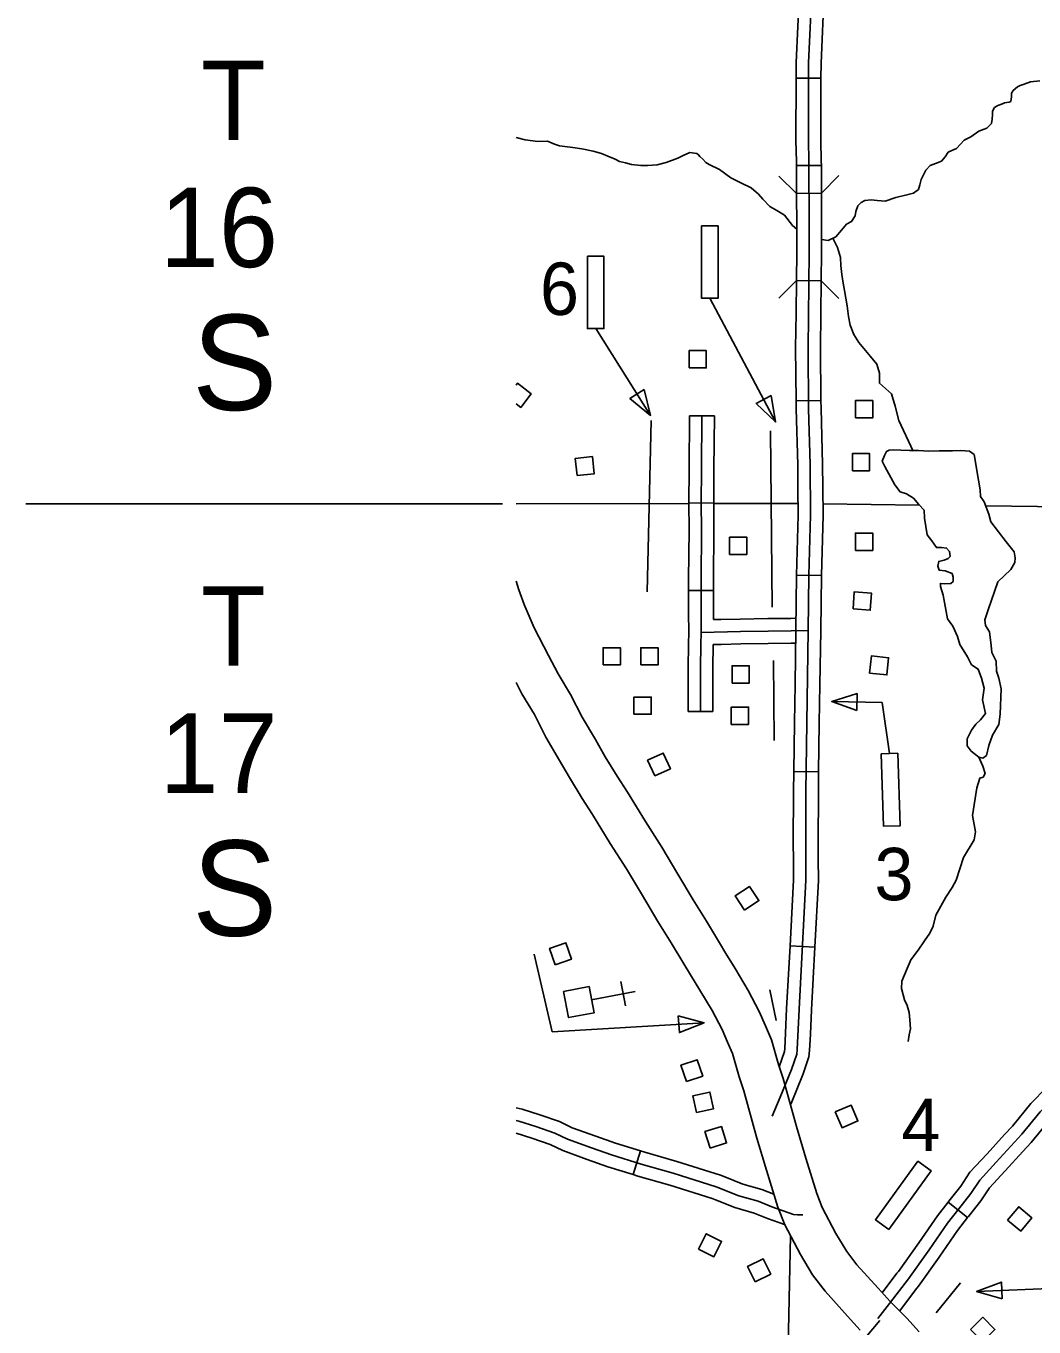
# Model space of a CAD drawing. Extents: x 61396 to 64680, y 55472 to 57605.
# Drawn here: x 61823 to 62013.4, y 56228.4 to 56474.2 of the extents above; entities that cross this region are included whole.
import ezdxf

# ---------------------------------------------------------------- set-up
doc = ezdxf.new("R2010")
doc.units = 0
for name, color, linetype in [('10', 7, 'Continuous'), ('31', 7, 'Continuous'), ('32', 7, 'Continuous'), ('35', 7, 'Continuous'), ('38', 7, 'Continuous'), ('4', 7, 'Continuous'), ('56', 7, 'Continuous'), ('57', 7, 'Continuous'), ('R_Border Notes', 7, 'Continuous')]:
    doc.layers.add(name, color=color, linetype=linetype)

msp = doc.modelspace()

# ---------------------------------------------------------------- linework, layer by layer
at = {"layer": '10'}
for points in [[(61915.57, 56369.32), (61916.11, 56367.7), (61917.13, 56364.9), (61919.02, 56360.49), (61921.72, 56355.3), (61923.52, 56351.83), (61925.86, 56347.92), (61928.07, 56343.61), (61930.55, 56339.39), (61932.4, 56336.16), (61934.64, 56332.45), (61936.63, 56329.45), (61940, 56323.91), (61943.08, 56319.06), (61946.13, 56313.95), (61949.05, 56309.13), (61951.52, 56305.1), (61953.99, 56301.03), (61955.18, 56299), (61956.98, 56296.16), (61959.42, 56292.03), (61960.13, 56290.68), (61961.52, 56288.06), (61962.72, 56285.33), (61963.81, 56282.68), (61965.17, 56278.03), (61966.06, 56275.35), (61968.55, 56266.29), (61970.34, 56260.35), (61972.38, 56253.66), (61973.43, 56251.02), (61976, 56246.11)], [(61969.28, 56242.13), (61966.32, 56247.75), (61965, 56251.07), (61962.86, 56258.08), (61961.04, 56264.13), (61958.59, 56273.07), (61957.71, 56275.7), (61956.43, 56280.09), (61955.53, 56282.27), (61954.48, 56284.65), (61953.23, 56287.02), (61952.6, 56288.2), (61950.31, 56292.08), (61948.51, 56294.94), (61947.28, 56297.04), (61944.85, 56301.03), (61942.38, 56305.06), (61939.44, 56309.92), (61936.42, 56314.96), (61933.37, 56319.78), (61930.03, 56325.26), (61928.04, 56328.27), (61925.66, 56332.2), (61923.79, 56335.47), (61921.22, 56339.85), (61919.03, 56344.13), (61916.69, 56348.02), (61915.57, 56350.18)], [(61976, 56246.11), (61978.03, 56242.7), (61979.97, 56240.21), (61983.98, 56235.75), (61986.26, 56233.24), (61989.38, 56230.08), (61991.73, 56227.55)], [(61980.58, 56227.86), (61978.18, 56230.51), (61973.97, 56235.19), (61971.56, 56238.29), (61969.28, 56242.13)]]:
    msp.add_lwpolyline(points, dxfattribs=at)
at = {"layer": '31'}
for p, q in [((61968.58, 56442.52), (61973.26, 56442.59)), ((61973.23, 56426.04), (61968.54, 56426.07)), ((61973.18, 56403.43), (61968.49, 56403.38)), ((61968.57, 56370.44), (61973.25, 56370.39)), ((61968.57, 56370.44), (61973.25, 56370.39)), ((61968.05, 56333.35), (61972.73, 56333.29)), ((61972.01, 56300.21), (61967.33, 56300.46)), ((61939.07, 56261.71), (61937.69, 56257.23)), ((62000.89, 56249.1), (61997.2, 56252))]:
    msp.add_line(p, q, dxfattribs=at)
for points in [[(61968.58, 56442.52), (61968.6, 56436.4)], [(61973.26, 56442.59), (61973.29, 56436.41)], [(61968.6, 56436.4), (61968.61, 56431.47), (61968.54, 56426.07)], [(61970.94, 56436.4), (61970.96, 56431.45), (61970.73, 56413.35), (61970.85, 56401.88), (61971.13, 56391.35), (61971.22, 56381.78), (61970.91, 56370.43), (61970.78, 56360)], [(61973.29, 56436.41), (61973.3, 56431.44), (61973.23, 56426.04)], [(61968.54, 56426.07), (61968.47, 56419.94)], [(61973.23, 56426.04), (61973.15, 56419.88)], [(61968.47, 56419.94), (61968.38, 56413.36), (61968.49, 56403.38)], [(61973.15, 56419.88), (61973.07, 56413.35), (61973.18, 56403.43)], [(61968.49, 56403.38), (61968.51, 56401.83), (61968.78, 56391.31), (61968.82, 56386.89)], [(61973.51, 56386.93), (61973.47, 56391.4), (61973.19, 56401.92), (61973.18, 56403.43)], [(61968.82, 56386.89), (61968.87, 56381.8), (61968.57, 56370.47), (61968.57, 56370.44)], [(61973.25, 56370.39), (61973.25, 56370.39), (61973.56, 56381.76), (61973.51, 56386.93)], [(61968.57, 56370.44), (61968.44, 56360.03)], [(61973.25, 56370.39), (61973.13, 56359.97)], [(61963.96, 56268.26), (61965.49, 56271.87), (61967.61, 56277.07), (61968.6, 56279.95), (61968.7, 56280.85), (61969.03, 56288.48), (61970.34, 56312.81), (61970.29, 56319.78), (61970.34, 56329.52), (61970.5, 56342.54), (61970.78, 56360)], [(61968.28, 56349.85), (61968.44, 56360.04)], [(61972.96, 56349.78), (61973.13, 56359.96)], [(61968.05, 56333.35), (61968.16, 56342.57), (61968.28, 56349.85)], [(61972.73, 56333.29), (61972.85, 56342.51), (61972.96, 56349.78)], [(61967.97, 56316.8), (61967.94, 56319.77), (61968, 56329.55), (61968.05, 56333.35)], [(61972.73, 56333.29), (61972.68, 56329.5), (61972.63, 56319.78), (61972.65, 56316.84)], [(61967.33, 56300.46), (61968, 56312.86), (61967.97, 56316.8)], [(61972.65, 56316.84), (61972.69, 56312.75), (61972.01, 56300.21)], [(61966.49, 56283.96), (61966.69, 56288.59), (61967.33, 56300.46)], [(61971.17, 56283.75), (61971.37, 56288.37), (61972.01, 56300.21)], [(62046.84, 56295.38), (62045.24, 56293.73), (62043.16, 56291.98), (62041.18, 56290.72), (62037.4, 56288.42), (62033.29, 56285.65), (62028.75, 56282.3), (62026.21, 56280.34), (62023.78, 56278.1), (62020.38, 56274.99), (62014.6, 56269.06), (62011.11, 56264.86), (62006.28, 56259.55), (62003.17, 56256.2), (62001.5, 56253.67), (61999.2, 56250.75), (61997.1, 56248.08), (61993.61, 56243.01), (61989.69, 56237.56), (61986.15, 56232.88), (61983.9, 56230.07)], [(61965.3, 56277.58), (61966.3, 56280.45), (61966.36, 56281.02), (61966.49, 56283.96)], [(61967.42, 56270.41), (61967.65, 56270.97), (61969.8, 56276.24), (61970.91, 56279.44), (61971.03, 56280.69), (61971.17, 56283.75)], [(62007.86, 56264.77), (62009.34, 56266.39), (62012.85, 56270.63), (62018.75, 56276.67), (62019.17, 56277.06)], [(62022.34, 56273.6), (62022.01, 56273.31), (62016.34, 56267.49), (62012.88, 56263.32), (62011.33, 56261.62)], [(61915.57, 56269.86), (61916.71, 56269.6), (61920.04, 56268.54), (61923.76, 56267.25), (61923.88, 56267.19)], [(61969.77, 56249.64), (61968.73, 56249.61), (61967.97, 56249.68), (61963.91, 56251.16), (61961.28, 56252.18), (61957.66, 56253.21), (61953.39, 56254.94), (61945.26, 56257.48), (61939.22, 56259.21), (61933.63, 56260.93), (61929.81, 56262.29), (61925.3, 56263.93), (61922.87, 56265.08), (61919.3, 56266.31), (61916.1, 56267.34), (61915.57, 56267.46)], [(61921.99, 56262.91), (61918.56, 56264.09), (61915.57, 56265.05)], [(61923.88, 56267.19), (61926.2, 56266.09), (61930.61, 56264.49), (61934.37, 56263.16), (61939.07, 56261.71)], [(61937.69, 56257.23), (61932.9, 56258.71), (61929.02, 56260.08), (61924.39, 56261.76), (61921.99, 56262.91)], [(61997.2, 56252), (61997.36, 56252.2), (61999.6, 56255.04), (62001.32, 56257.66), (62004.55, 56261.14), (62007.86, 56264.77)], [(61955.03, 56256.8), (61954.18, 56257.14), (61945.93, 56259.73), (61939.89, 56261.45), (61939.07, 56261.71)], [(62011.33, 56261.62), (62008, 56257.96), (62005.02, 56254.75), (62003.4, 56252.3), (62001.05, 56249.31), (62000.89, 56249.1)], [(61953.27, 56252.46), (61952.6, 56252.73), (61944.59, 56255.24), (61938.55, 56256.96), (61937.69, 56257.23)], [(61964.25, 56253.54), (61962.03, 56254.41), (61958.43, 56255.43), (61955.03, 56256.8)], [(61966.31, 56247.79), (61963.08, 56248.96), (61960.53, 56249.96), (61956.9, 56250.99), (61953.27, 56252.46)], [(61997.2, 56252), (61995.21, 56249.47), (61991.69, 56244.36), (61987.8, 56238.95), (61987.53, 56238.58)], [(62000.89, 56249.1), (61998.99, 56246.69), (61995.53, 56241.66), (61991.58, 56236.17), (61991.27, 56235.76)], [(61987.53, 56238.58), (61984.75, 56234.9)], [(61991.27, 56235.76), (61988.02, 56231.46)], [(61930.45, 56183.74), (61933.97, 56184.15), (61937.57, 56184.89), (61940, 56186.02), (61943.65, 56188.21), (61947.9, 56191.9), (61951.41, 56194.9), (61959.17, 56201.91), (61965.24, 56207.61), (61969.78, 56212.7), (61976.27, 56219.95), (61980.01, 56224.58), (61984.28, 56229.68)]]:
    msp.add_lwpolyline(points, dxfattribs=at)
at = {"layer": '32'}
for p, q in [((61968.49, 56464.33), (61973.18, 56464.31)), ((61968.56, 56447.81), (61973.25, 56447.83)), ((61948.35, 56400.57), (61953.04, 56400.53)), ((61948.22, 56384.03), (61952.91, 56384.08)), ((61948.17, 56367.55), (61952.86, 56367.55)), ((61952.77, 56344.72), (61948.08, 56344.72))]:
    msp.add_line(p, q, dxfattribs=at)
for points in [[(62009.57, 56550.11), (62005.52, 56536.02), (62001.49, 56522.36), (62000.08, 56516.98), (61999.59, 56515.45), (61998.01, 56513.39), (61992.08, 56507.78), (61983.37, 56500.49), (61976.84, 56495.43), (61974.77, 56493.31), (61973.36, 56490.86), (61972.6, 56488.52), (61971.52, 56481.91), (61970.84, 56467.24), (61970.79, 56452.56), (61970.9, 56448.61), (61970.94, 56436.4)], [(61969.13, 56480.91), (61968.5, 56467.3), (61968.49, 56464.33)], [(61973.81, 56480.7), (61973.19, 56467.18), (61973.18, 56464.31)], [(61968.49, 56464.33), (61968.44, 56452.53), (61968.56, 56448.57), (61968.56, 56447.81)], [(61973.18, 56464.31), (61973.13, 56452.59), (61973.24, 56448.65), (61973.25, 56447.83)], [(61968.56, 56447.81), (61968.58, 56442.52)], [(61973.25, 56447.83), (61973.26, 56442.59)], [(61948.35, 56400.57), (61948.25, 56390.44), (61948.22, 56384.12), (61948.22, 56384.03)], [(61950.69, 56400.55), (61950.59, 56390.42), (61950.57, 56384.13), (61950.62, 56379), (61950.51, 56369.59), (61950.51, 56363.35), (61950.54, 56359.64)], [(61953.04, 56400.53), (61952.94, 56390.4), (61952.91, 56384.14), (61952.91, 56384.08)], [(61948.22, 56384.03), (61948.27, 56379), (61948.17, 56369.6), (61948.17, 56367.55)], [(61952.91, 56384.08), (61952.96, 56379), (61952.86, 56369.58), (61952.86, 56367.55)], [(61948.17, 56367.55), (61948.17, 56363.34), (61948.19, 56359.69)], [(61952.86, 56367.55), (61952.86, 56363.36), (61952.87, 56362.04)], [(61954.23, 56362.07), (61952.87, 56362.04)], [(61968.47, 56362.3), (61967.49, 56362.29), (61963.16, 56362.23), (61957.92, 56362.16), (61954.23, 56362.07)], [(61948.08, 56344.72), (61948.08, 56349.21), (61948.08, 56352.89), (61948.14, 56357.4), (61948.19, 56359.69)], [(61950.43, 56344.72), (61950.43, 56349.21), (61950.43, 56352.87), (61950.48, 56357.36), (61950.54, 56359.64)], [(61970.78, 56360), (61967.52, 56359.94), (61963.19, 56359.89), (61957.96, 56359.81), (61950.54, 56359.64)], [(61952.77, 56344.72), (61952.77, 56349.21), (61952.77, 56352.86), (61952.83, 56357.35)], [(61954.34, 56357.38), (61952.83, 56357.35)], [(61968.4, 56357.61), (61967.55, 56357.6), (61963.22, 56357.55), (61958.01, 56357.47), (61954.34, 56357.38)]]:
    msp.add_lwpolyline(points, dxfattribs=at)
at = {"layer": '35'}
for points in [[(62014.55, 56463.82), (62012.79, 56463.61), (62011.56, 56463.2), (62010.8, 56462.91), (62010.33, 56462.7), (62009.5, 56461.97), (62009.14, 56461.5), (62009.15, 56460.78), (62009.04, 56459.94), (62008.75, 56459.76), (62007.88, 56459.68), (62007.49, 56459.44), (62006.61, 56459.15), (62005.97, 56458.76), (62005.61, 56458.11), (62005.57, 56457.45), (62005.52, 56456.6), (62005.37, 56455.73), (62004.5, 56454.87), (62003.02, 56454.28), (62001.46, 56453.22), (62000.25, 56452.59), (61998.78, 56451.03), (61997.89, 56450.67), (61997.22, 56450.31), (61996.64, 56449.48), (61995.93, 56448.62), (61994.82, 56448.17), (61993.78, 56447.82), (61992.98, 56446.93), (61992.12, 56445.17), (61991.88, 56444.14), (61991.58, 56443.3), (61990.65, 56442.57), (61989.42, 56442.28), (61987.34, 56441.8), (61985.29, 56441.1), (61983.79, 56441.23)], [(61968.61, 56435.77), (61967.81, 56436.48), (61966.26, 56438.43), (61964.81, 56439.35), (61963.52, 56440.1), (61962.17, 56441.45), (61961.35, 56442.39), (61959.97, 56443.58), (61958.02, 56444.57), (61956.17, 56445.5), (61954.01, 56447.09), (61952.06, 56447.98), (61951.42, 56448.41), (61950.84, 56448.99), (61950.29, 56449.5), (61950.04, 56449.85), (61949.7, 56450.08), (61948.43, 56450.27), (61947.16, 56449.71), (61946.15, 56449.2), (61943.94, 56448.41), (61942.2, 56447.95), (61940.48, 56447.8), (61939.13, 56447.84), (61937.38, 56448.04), (61936.23, 56448.35), (61935.08, 56448.56), (61934.28, 56449.02), (61932.88, 56449.59), (61931.71, 56450.06), (61930.12, 56450.54), (61927.97, 56450.94), (61926.29, 56451.23), (61923.76, 56451.55), (61922.8, 56451.88), (61921.53, 56452.39), (61919.71, 56452.37), (61917.31, 56452.65), (61915.6, 56453.13), (61915.57, 56453.13)], [(61983.79, 56441.23), (61982.64, 56441.32), (61981.48, 56441.19), (61980.75, 56440.83), (61980.14, 56440.22), (61979.74, 56439.13), (61979.65, 56438.32), (61978.97, 56437.24), (61977.99, 56436.73), (61977.05, 56435.62), (61975.96, 56434.33), (61974.56, 56433.68), (61973.25, 56433.87)], [(61975.42, 56434.09), (61976.28, 56432.31), (61976.86, 56430.45), (61976.95, 56428.91), (61977.1, 56427.21), (61977.34, 56425.6), (61977.65, 56424.18), (61978.15, 56421.34), (61978.35, 56419.3), (61978.68, 56417.66), (61979.39, 56415.91), (61980.32, 56414.38), (61981.57, 56412.88), (61982.54, 56411.75), (61983.73, 56410.31), (61984.25, 56408.57), (61984.24, 56406.72), (61986.48, 56404.68), (61987.2, 56402.36), (61987.91, 56399.68), (61990.61, 56393.85)], [(62002.1, 56393.21), (62001.21, 56393.85), (61999.63, 56394), (61998, 56393.9), (61995.53, 56393.9), (61993.51, 56393.85), (61991.58, 56394), (61989.9, 56394), (61988.27, 56394.04), (61986.94, 56394.09), (61986.05, 56394.04), (61985.55, 56393.8), (61985.16, 56393.06), (61984.76, 56391.97), (61985.21, 56390.98), (61987.13, 56387.48), (61988.12, 56386.19), (61989.31, 56385.8), (61990.64, 56384.96), (61991.68, 56383.82), (61992.67, 56382.73), (61992.76, 56381.2), (61993.21, 56378.04), (61994.1, 56376.91), (61994.99, 56375.67), (61995.93, 56375.67), (61996.91, 56375.57), (61997.46, 56374.93), (61997.56, 56373.99), (61997.21, 56373.6), (61996.47, 56373.3), (61995.43, 56373.05), (61995.28, 56372.16), (61995.53, 56371.37), (61996.67, 56371.27), (61997.95, 56370.73), (61998.15, 56370.09), (61998.15, 56369.25), (61997.7, 56368.85), (61996.52, 56368.8), (61995.73, 56368.9), (61995.73, 56368.31), (61996.27, 56366.68), (61997.11, 56362.19), (61998.1, 56360.8), (61998.94, 56358.83), (61999.43, 56357.35), (62000.87, 56355.02), (62001.61, 56353.54), (62002.89, 56352.7), (62003.53, 56350.97), (62004.03, 56349.1), (62003.68, 56346.92), (62004.23, 56344.31), (62003.29, 56343.12), (62002.45, 56342.33), (62001.61, 56341.19), (62000.82, 56339.56), (62000.82, 56338.23), (62001.56, 56337.19), (62002.99, 56336.06), (62003.78, 56335.91), (62004.42, 56336.4), (62004.92, 56338.28), (62005.56, 56340.21), (62006.75, 56342.23), (62007.04, 56344.16), (62007.19, 56349), (62006.79, 56351.02), (62006.35, 56352.31), (62006.25, 56354.18), (62005.46, 56355.81), (62005.36, 56357.15), (62005.02, 56359.72), (62004.28, 56360.95), (62004.13, 56361.99), (62004.77, 56363.87), (62006.6, 56369.2), (62009.02, 56371.52), (62009.81, 56372.81), (62009.86, 56373.69), (62009.66, 56374.83), (62008.18, 56376.76), (62005.26, 56380.51), (62004.92, 56381.99), (62004.03, 56384.27), (62003.29, 56385.3), (62003.24, 56386.59), (62002.94, 56388.36), (62002.1, 56393.21)], [(62002.99, 56336.06), (62003.75, 56334.36), (62004.18, 56332.96), (62003.8, 56332.29), (62003.17, 56332.1), (62002.64, 56330.26), (62001.82, 56325.06), (62002.35, 56321.97), (62002.11, 56320.43), (62000.13, 56317.1), (61998.74, 56312.81), (61997.96, 56311.46), (61996.76, 56309.63), (61994.86, 56306.22), (61994.36, 56304.17), (61993.77, 56302.83), (61992.72, 56301.35), (61991.52, 56299.59), (61990.14, 56297.76), (61990.02, 56297.47), (61989.44, 56296.13), (61988.48, 56293.75), (61988.39, 56292.37), (61988.96, 56290.22), (61989.46, 56289.14), (61989.82, 56287.86), (61989.98, 56286.45), (61990.07, 56284.73), (61989.82, 56283.65), (61989.67, 56282.36)]]:
    msp.add_lwpolyline(points, dxfattribs=at)
at = {"layer": '38'}
for points in [[(61968.58, 56442.52), (61965.22, 56445.79)], [(61976.53, 56445.95), (61973.26, 56442.59)], [(61965.21, 56422.78), (61968.54, 56426.07)], [(61973.23, 56426.04), (61976.53, 56422.7)]]:
    msp.add_lwpolyline(points, dxfattribs=at)
at = {"layer": '4'}
for points in [[(61948.22, 56383.95), (61915.57, 56383.94)], [(61968.85, 56383.96), (61952.91, 56383.95)], [(61991.8, 56383.69), (61973.54, 56383.92)], [(62195.89, 56380.52), (62121.79, 56382.05), (62121.21, 56382.06), (62004.31, 56383.53)], [(61967.44, 56245.63), (61966.93, 56221.8), (61966.92, 56218.25), (61966.91, 56213.01)]]:
    msp.add_lwpolyline(points, dxfattribs=at)
at = {"layer": '56'}
for points in [[(61950.62, 56436.42), (61953.75, 56436.42), (61953.75, 56422.75), (61950.62, 56422.75)], [(61929.05, 56430.68), (61932.18, 56430.68), (61932.18, 56417.01), (61929.05, 56417.01)], [(61948.25, 56409.6), (61948.25, 56412.85), (61951.51, 56412.85), (61951.51, 56409.6)], [(61939.78, 56405.51), (61937.08, 56403.8), (61940.99, 56400.61)], [(61963.76, 56404.37), (61960.94, 56402.88), (61964.59, 56399.4)], [(61979.68, 56400.16), (61979.68, 56403.41), (61982.95, 56403.41), (61982.95, 56400.16)], [(61927.09, 56389.27), (61926.76, 56392.51), (61930.01, 56392.83), (61930.33, 56389.6)], [(61979.11, 56390.16), (61979.11, 56393.41), (61982.37, 56393.41), (61982.37, 56390.16)], [(61979.69, 56375.13), (61979.69, 56378.39), (61982.95, 56378.39), (61982.95, 56375.13)], [(61955.92, 56374.35), (61955.92, 56377.6), (61959.18, 56377.6), (61959.18, 56374.35)], [(61979.23, 56364.06), (61979.46, 56367.31), (61982.72, 56367.07), (61982.49, 56363.83)], [(61932.02, 56353.49), (61932.02, 56356.74), (61935.28, 56356.74), (61935.28, 56353.49)], [(61939.13, 56353.49), (61939.13, 56356.74), (61942.4, 56356.74), (61942.4, 56353.49)], [(61956.37, 56350.07), (61956.37, 56353.33), (61959.63, 56353.33), (61959.63, 56350.07)], [(61982.37, 56351.94), (61982.69, 56355.18), (61985.94, 56354.85), (61985.62, 56351.62)], [(61937.84, 56344.18), (61937.84, 56347.43), (61941.1, 56347.43), (61941.1, 56344.18)], [(61979.94, 56344.89), (61980.01, 56348.08), (61975.2, 56346.59)], [(61956.23, 56342.27), (61956.23, 56345.53), (61959.5, 56345.53), (61959.5, 56342.27)], [(61941.76, 56332.54), (61940.41, 56335.5), (61943.38, 56336.85), (61944.73, 56333.89)], [(61984.55, 56336.69), (61987.68, 56336.8), (61988.15, 56323.13), (61985.02, 56323.02)], [(61958.75, 56307.16), (61956.94, 56309.86), (61959.66, 56311.67), (61961.46, 56308.97)], [(61922.93, 56296.87), (61921.9, 56299.96), (61925, 56300.99), (61926.03, 56297.91)], [(61946.22, 56287.22), (61946.42, 56284.04), (61951.09, 56285.92)], [(61947.74, 56274.81), (61946.71, 56277.89), (61949.8, 56278.92), (61950.83, 56275.84)], [(61949.67, 56268.94), (61948.99, 56272.12), (61952.18, 56272.8), (61952.86, 56269.62)], [(61975.86, 56269.08), (61978.85, 56270.36), (61980.14, 56267.36), (61977.15, 56266.08)], [(61952.23, 56262.23), (61951.26, 56265.34), (61954.38, 56266.31), (61955.35, 56263.2)], [(61985.98, 56246.87), (61983.45, 56248.71), (61991.49, 56259.76), (61994.02, 56257.93)], [(62008.44, 56248.64), (62010.53, 56251.14), (62013.03, 56249.05), (62010.95, 56246.55)], [(61950.03, 56243.16), (61951.49, 56246.06), (61954.41, 56244.61), (61952.95, 56241.7)], [(61960.77, 56236.97), (61959.32, 56239.88), (61962.23, 56241.34), (61963.69, 56238.43)], [(62007.41, 56233.76), (62007.28, 56236.94), (62002.57, 56235.15)], [(62001.43, 56227.98), (62003.73, 56230.28), (62006.04, 56227.97), (62003.74, 56225.67)]]:
    msp.add_lwpolyline(points, close=True, dxfattribs=at)
for points in [[(61952.19, 56422.75), (61964.59, 56399.4)], [(61930.61, 56417.01), (61940.99, 56400.61)], [(61915.57, 56406.35), (61915.83, 56406.69), (61918.42, 56404.71), (61916.44, 56402.13), (61915.57, 56402.8)], [(61941.12, 56399.63), (61940.31, 56367.29)], [(61963.64, 56397.7), (61963.97, 56364.38)], [(61964.19, 56354.35), (61964.32, 56339.19)], [(61986.11, 56336.74), (61984.73, 56346.38), (61975.2, 56346.59)], [(61918.98, 56298.86), (61922.37, 56284.17)], [(61963.52, 56292.15), (61964.71, 56286.36)], [(61922.37, 56284.17), (61951.09, 56285.92)], [(61999.52, 56236.77), (61994.95, 56231.12)], [(62022.49, 56235.96), (62002.57, 56235.15)]]:
    msp.add_lwpolyline(points, dxfattribs=at)
at = {"layer": '57'}
for p, q in [((61938.09, 56291.82), (61929.83, 56290.26)), ((61935.36, 56293.69), (61936.23, 56289.08))]:
    msp.add_line(p, q, dxfattribs=at)
msp.add_lwpolyline([(61924.56, 56291.84), (61929.36, 56292.75), (61930.3, 56287.78), (61925.5, 56286.87)], close=True, dxfattribs=at)
at = {"layer": 'R_Border Notes'}
msp.add_line((61913, 56383.94), (61822.98, 56383.94), dxfattribs=at)

# ---------------------------------------------------------------- texts
at = {"layer": '56'}
for s, p in [('6', (61920.09, 56419.59)), ('3', (61983.28, 56309.04)), ('4', (61988.39, 56261.68))]:
    msp.add_text(s, height=9.9, dxfattribs=at).set_placement(p)
at = {"layer": 'R_Border Notes'}
for s, height, p in [('T', 15, (61856.05, 56452.63)), ('16', 15, (61848.27, 56428.63)), ('S', 18, (61854.38, 56401.63)), ('T', 15, (61856.05, 56353.33)), ('17', 15, (61848.23, 56329.33)), ('S', 18, (61854.38, 56302.33))]:
    msp.add_text(s, height=height, dxfattribs=at).set_placement(p)

doc.saveas('drawing.dxf')
